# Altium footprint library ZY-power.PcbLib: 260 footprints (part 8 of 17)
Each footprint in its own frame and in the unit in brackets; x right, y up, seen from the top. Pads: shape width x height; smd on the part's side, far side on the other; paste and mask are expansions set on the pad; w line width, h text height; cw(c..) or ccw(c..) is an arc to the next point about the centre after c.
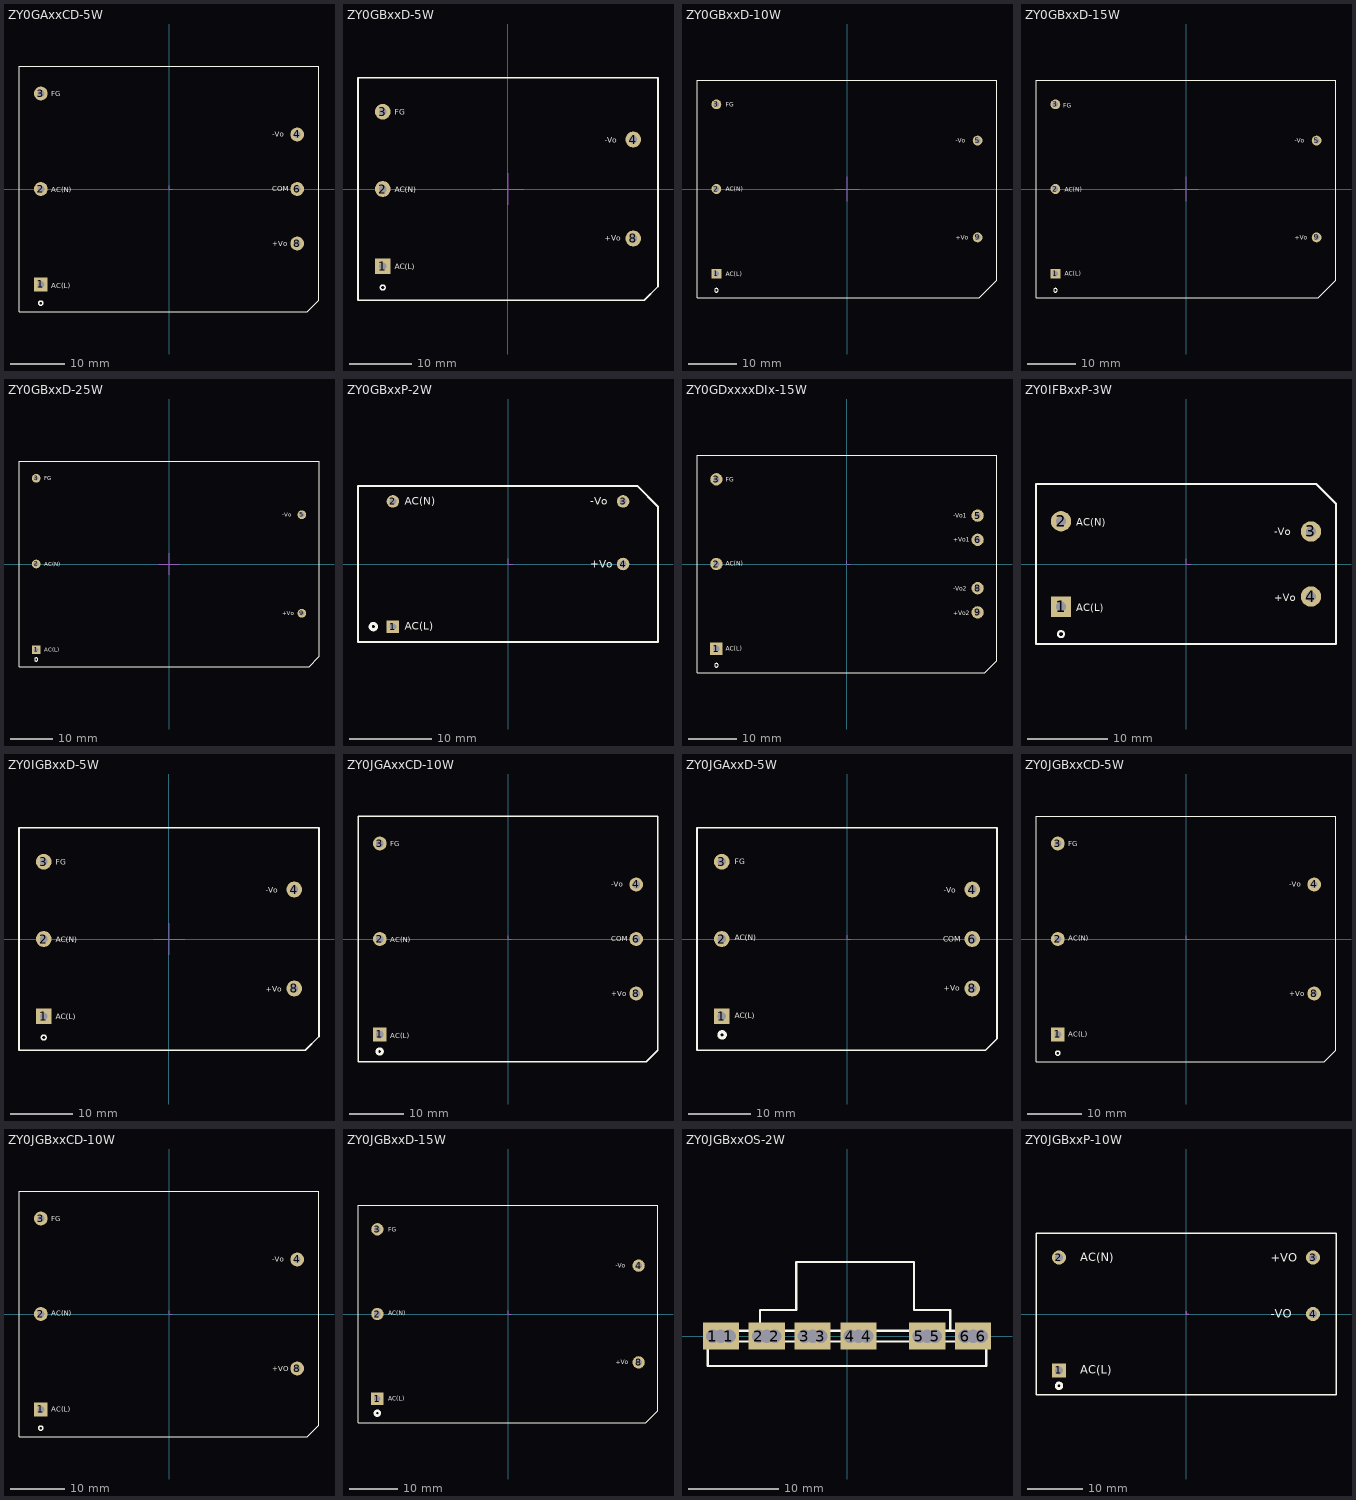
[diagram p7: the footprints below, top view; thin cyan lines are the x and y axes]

## ZY0GAxxCD-5W [mm]
height 20.5
pads (6):
  rect 2.54x2.54 hole 1.27: 1(-23.5,-17.5)
  round 2.54 hole 1.27: 2(-23.5,0) 3(-23.5,17.5) 4(23.5,10) 6(23.5,0) 8(23.5,-10)
Top Overlay:
  circle w0.254: c-23.5,-20.929 r0.381
  lines w0.127: -27.5,-22.5 -27.5,22.5 27.5,22.5 27.5,-20.379 25.379,-22.5 -27.5,-22.5
  text "AC(L)" at -21.595,-18.186 h0.91
  text "AC(N)" at -21.595,-0.572 h0.91
  text "FG" at -21.595,17.043 h0.91
  text "+Vo" at 18.928,-10.541 h0.91
  text "COM" at 18.928,-0.457 h0.91
  text "-Vo" at 18.928,9.601 h0.91
Mechanical 15:
  lines w0.127: 0,0.635 0,0 0.635,0

## ZY0GBxxD-5W [mm] "120426 修改 by kong"
height 20
pads (5):
  rect 2.54x2.54 hole 1.27: 1(-20.25,-12.5)
  round 2.54 hole 1.27: 2(-20.25,0) 3(-20.25,12.5) 4(20.25,8) 8(20.25,-8)
Top Overlay:
  circle w0.254: c-20.25,-15.929 r0.381
  lines w0.254: 22.033,-18 -24.25,-18 -24.25,18 24.25,18 24.25,-15.773 22.033,-17.991
  text "AC(L)" at -18.345,-13.008 h0.91
  text "AC(N)" at -18.345,-0.562 h0.91
  text "FG" at -18.345,12.011 h0.91
  text "+Vo" at 15.678,-8.381 h0.91
  text "-Vo" at 15.678,7.439 h0.91
Mechanical 15:
  lines w0.152: -2.54,0 2.54,0 ; 0,-2.54 0,2.54

## ZY0GBxxD-10W [mil] "120426 修改 by kong"
height 885.83
pads (5):
  rect 80x80 hole 45: 1(-1062.99,-688.98)
  round 80 hole 45: 2(-1062.99,0) 3(-1062.99,688.98) 5(1062.99,393.7) 9(1062.99,-393.7)
Top Overlay:
  circle w10: c-1062.99,-823.98 r15
  lines w10: -1220.47,-885.83 -1220.47,885.83 1220.47,885.83 1220.47,-741.14 1075.79,-885.83 -1220.47,-885.83
  text "-Vo" at 882.99,376.3 h36
  text "+Vo" at 882.99,-413.7 h36
  text "FG" at -987.99,671.02 h36
  text "AC(N)" at -987.99,-18.98 h36
  text "AC(L)" at -987.99,-708.98 h36
Mechanical 15:
  lines w6: -100,0 100,0 ; 0,-100 0,100

## ZY0GBxxD-15W [mil] "120426 修改 by kong"
height 885.83
pads (5):
  rect 80x80 hole 45: 1(-1062.99,-688.98)
  round 80 hole 45: 2(-1062.99,0) 3(-1062.99,688.98) 5(1062.99,393.7) 9(1062.99,-393.7)
Top Overlay:
  circle w10: c-1062.99,-823.98 r15
  lines w10: -1220.47,-885.83 1075.79,-885.83 1220.47,-741.14 1220.47,885.83 -1220.47,885.83 -1220.47,-885.83
  text "AC(L)" at -987.99,-703.98 h36
  text "AC(N)" at -987.99,-23.98 h36
  text "FG" at -997.99,661.02 h36
  text "+Vo" at 882.99,-413.7 h36
  text "-Vo" at 882.99,375 h36
Mechanical 15:
  lines w6: -100,0 100,0 ; 0,-100 0,100

## ZY0GBxxD-25W [mil] "120426 修改 by kong"
height 925.2
pads (5):
  rect 80x80 hole 45: 1(-1220.47,-787.4)
  round 80 hole 45: 2(-1220.47,0) 3(-1220.47,787.4) 5(1220.47,452.76) 9(1220.47,-452.76)
Top Overlay:
  circle w10: c-1220.47,-877.4 r15
  lines w10: -1377.95,-944.88 -1377.95,944.88 1377.95,944.88 1377.95,-853.98 1287.05,-944.88 -1377.95,-944.88
  text "-Vo" at 1040.47,432.6 h36
  text "+Vo" at 1040.47,-472.4 h36
  text "FG" at -1145.47,767.6 h36
  text "AC(N)" at -1145.47,-22.4 h36
  text "AC(L)" at -1145.47,-807.4 h36
Mechanical 15:
  lines w6: -100,0 100,0 ; 0,-100 0,100

## ZY0GBxxP-2W [mil]
height 669.29
pads (4):
  rect 60x60 hole 32: 1(-551.18,-300)
  round 60 hole 32: 2(-551.18,300) 3(551.18,300) 4(551.18,0)
Top Overlay:
  circle w15: c-645,-300 r15
  lines w10: -718.5,-374.02 718.5,-374.02 718.5,274.02 618.5,374.02 -718.5,374.02 -718.5,-374.02
  text "AC(L)" at -495,-316 h36
  text "+Vo" at 395,-19 h36
  text "-Vo" at 395,284 h36
  text "AC(N)" at -495,283 h36
Mechanical 15:
  lines w5: 0,25 0,0 25,0

## ZY0GDxxxxDIx-15W [mm]
height 22.5
pads (7):
  rect 2.54x2.54 hole 1.27: 1(-27,-17.5)
  round 2.54 hole 1.27: 2(-27,0) 3(-27,17.5) 5(27,10) 6(27,5) 8(27,-5) 9(27,-10)
Top Overlay:
  circle w0.254: c-27,-20.929 r0.381
  lines w0.127: -31,-22.5 -31,22.5 31,22.5 31,-19.978 28.478,-22.5 -31,-22.5
  text "FG" at -25.095,16.993 h0.91
  text "AC(N)" at -25.095,-0.406 h0.91
  text "AC(L)" at -25.095,-17.932 h0.91
  text "-Vo1" at 21.92,9.576 h0.91
  text "+Vo1" at 21.92,4.594 h0.91
  text "-Vo2" at 21.92,-5.566 h0.91
  text "+Vo2" at 21.92,-10.566 h0.91
Mechanical 15:
  lines w0.127: 0,0.635 0,0 0.635,0

## ZY0IFBxxP-3W [mm]
pads (4):
  rect 2.54x2.54 hole 1.27: 1(-15.62,-5.335)
  round 2.54 hole 1.27: 2(-15.62,5.335) 3(15.62,4.065) 4(15.62,-4.065)
Top Overlay:
  circle w0.254: c-15.62,-8.764 r0.381
  lines w0.254: -18.75,-10 -18.75,10 16.289,10 18.75,7.539 18.75,-10 -18.75,-10
  text "AC(L)" at -13.715,-5.893 h0.91
  text "AC(N)" at -13.715,4.775 h0.91
  text "-Vo" at 11.048,3.589 h0.91
  text "+Vo" at 11.048,-4.666 h0.91
Mechanical 15:
  lines w0.127: 0,0.635 0,0 0.635,0

## ZY0IGBxxD-5W [mm] "120426 修改 by kong"
height 20
pads (5):
  rect 2.54x2.54 hole 1.27: 1(-20.25,-12.5)
  round 2.54 hole 1.27: 2(-20.25,0) 3(-20.25,12.5) 4(20.25,8) 8(20.25,-8)
Top Overlay:
  circle w0.254: c-20.25,-15.929 r0.381
  lines w0.254: 22.033,-18 -24.25,-18 -24.25,18 24.25,18 24.25,-15.773 22.033,-17.991
  text "AC(L)" at -18.345,-13.008 h0.91
  text "AC(N)" at -18.345,-0.562 h0.91
  text "FG" at -18.345,12.011 h0.91
  text "+Vo" at 15.678,-8.563 h0.91
  text "-Vo" at 15.678,7.439 h0.91
Mechanical 15:
  lines w0.152: -2.54,0 2.54,0 ; 0,-2.54 0,2.54

## ZY0JGAxxCD-10W [mm]
height 20.5
pads (6):
  rect 2.54x2.54 hole 1.397: 1(-23.5,-17.5)
  round 2.54 hole 1.397: 2(-23.5,0) 3(-23.5,17.5) 4(23.5,10) 6(23.5,0) 8(23.5,-10)
Top Overlay:
  circle w0.508: c-23.52,-20.625 r0.508
  lines w0.254: -27.5,-22.5 -27.5,22.5 27.5,22.5 27.5,-20.379 25.379,-22.5 -27.5,-22.5
  text "AC(L)" at -21.595,-18.186 h0.91
  text "AC(N)" at -21.595,-0.572 h0.91
  text "FG" at -21.595,17.043 h0.91
  text "+Vo" at 18.928,-10.541 h0.91
  text "COM" at 18.928,-0.457 h0.91
  text "-Vo" at 18.928,9.601 h0.91
Mechanical 15:
  lines w0.127: 0,0.635 0,0 0.635,0

## ZY0JGAxxD-5W [mm]
height 20.5
pads (6):
  rect 2.54x2.54 hole 1.397: 1(-20.25,-12.5)
  round 2.54 hole 1.397: 2(-20.25,0) 3(-20.25,12.5) 4(20.25,8) 6(20.25,0) 8(20.25,-8)
Top Overlay:
  circle w0.508: c-20.193,-15.494 r0.508
  lines w0.254: -24.25,-18 22.386,-18 24.25,-16.136 24.25,18 -24.25,18 -24.25,-18
  text "COM" at 15.538,-0.445 h0.91
  text "AC(L)" at -18.161,-12.827 h0.91
  text "AC(N)" at -18.161,-0.229 h0.91
  text "FG" at -18.161,12.065 h0.91
  text "+Vo" at 15.621,-8.382 h0.91
  text "-Vo" at 15.621,7.493 h0.91
Mechanical 15:
  lines w0.127: 0,0.635 0,0 0.635,0

## ZY0JGBxxCD-5W [mm]
pads (5):
  rect 2.54x2.54 hole 1.27: 1(-23.5,-17.5)
  round 2.54 hole 1.27: 2(-23.5,0) 3(-23.5,17.5) 4(23.5,10) 8(23.5,-10)
Top Overlay:
  circle w0.254: c-23.5,-20.929 r0.381
  lines w0.127: -27.5,-22.5 -27.5,22.5 27.5,22.5 27.5,-20.379 25.379,-22.5 -27.5,-22.5
  text "AC(L)" at -21.595,-17.882 h0.91
  text "AC(N)" at -21.595,-0.356 h0.91
  text "FG" at -21.595,17.043 h0.91
  text "+Vo" at 18.928,-10.516 h0.91
  text "-Vo" at 18.928,9.55 h0.91
Mechanical 15:
  lines w0.127: 0,0.635 0,0 0.635,0

## ZY0JGBxxCD-10W [mm]
pads (5):
  rect 2.54x2.54 hole 1.27: 1(-23.5,-17.5)
  round 2.54 hole 1.27: 2(-23.5,0) 3(-23.5,17.5) 4(23.5,10) 8(23.5,-10)
Top Overlay:
  circle w0.254: c-23.5,-20.929 r0.381
  lines w0.127: -27.5,-22.5 -27.5,22.5 27.5,22.5 27.5,-20.379 25.379,-22.5 -27.5,-22.5
  text "AC(L)" at -21.595,-17.882 h0.91
  text "AC(N)" at -21.595,-0.356 h0.91
  text "FG" at -21.595,17.043 h0.91
  text "+VO" at 18.928,-10.516 h0.91
  text "-Vo" at 18.928,9.55 h0.91
Mechanical 15:
  lines w0.127: 0,0.635 0,0 0.635,0

## ZY0JGBxxD-15W [mm]
height 22.5
pads (5):
  rect 2.54x2.54 hole 1.397: 1(-27,-17.5)
  round 2.54 hole 1.397: 2(-27,0) 3(-27,17.5) 4(27,10) 8(27,-10)
Top Overlay:
  circle w0.508: c-27,-20.498 r0.508
  lines w0.254: -31,-22.5 -31,22.5 31,22.5 31,-20.003 28.503,-22.5 -31,-22.5
  text "AC(L)" at -24.719,-17.882 h0.91
  text "AC(N)" at -24.719,-0.267 h0.91
  text "FG" at -24.719,17.043 h0.91
  text "+Vo" at 22.276,-10.389 h0.91
  text "-Vo" at 22.276,9.55 h0.91
Mechanical 15:
  lines w0.127: 0,0.635 0,0 0.635,0

## ZY0JGBxxOS-2W [mm]
height 17.2
pads (18):
  rect 2.2x3 hole 1.5 square: 1(-14.87,0) 1(-13.075,0) 2(-9.79,0) 2(-7.995,0) 3(-4.71,0) 3(-2.915,0) 4(0.37,0) 4(2.165,0) 5(7.99,0) 5(9.785,0) 6(13.07,0) 6(14.865,0)
  round 0 hole 1.5 square: 1(-13.97,0) 2(-8.89,0) 3(-3.81,0) 4(1.27,0) 5(8.89,0) 6(13.97,0)
Top Overlay:
  lines w0.254: -15.42,-0.6 0,-0.6 15.42,-0.6 ; -9.63,0.6 -9.63,2.9 -5.63,2.9 -5.63,8.2 7.43,8.2 7.43,2.9 11.43,2.9 11.43,0.6 ; -15.42,-3.3 -15.42,0.6 0,0.6 15.42,0.6 15.42,-3.3 0,-3.3 -15.42,-3.3

## ZY0JGBxxP-10W [mil]
height 748.03
pads (4):
  rect 100x100 hole 55: 1(-900,-400)
  round 100 hole 55: 2(-900,400) 3(900,400) 4(900,0)
Top Overlay:
  circle w20: c-900,-509 r20
  lines w10: -1062.99,-570.87 -1062.99,570.87 1062.99,570.87 1062.99,-570.87 -1062.99,-570.87
  text "AC(L)" at -750,-425 h60
  text "AC(N)" at -750,375 h60
  text "+VO" at 600,370.87 h60
  text "-VO" at 600,-25 h60
Mechanical 15:
  lines w10: 0,20 0,0 20,0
